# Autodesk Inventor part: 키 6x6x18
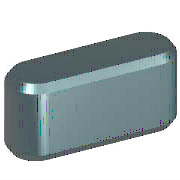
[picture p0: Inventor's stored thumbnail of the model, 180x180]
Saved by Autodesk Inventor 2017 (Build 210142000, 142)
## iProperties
IsCustomPart: 0
Created: 2012-02
Part Number: 키 6x6x18
Material: 강철, 연강
Document SubType Name: Modeling
Standard: JIS B 1301
Designer: mdu
Standards Organization: JIS
Language: ko-KR
Size Designation: 6x6x18
Categories: <MemberInstance><Categories><Category DisplayName="샤프트 부품" InternalName="7f7aeb1f-a693-4053-b835-cee3144e0d98" Mnemonic="SHFT"><Category DisplayName="키" Interna
Density: 1 g/cm^3
Appearance: 보라색
Author: mdu
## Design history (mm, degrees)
workplane "Work Plane1"
workplane "Work Plane2"
sketch "스케치1"
  geometry: L1 (3, 3)-(15, 3); L2 (15, -3)-(3, -3); L3 (0, 9.4)-(0, -7.4) reference; L4 (-5, 0)-(30, 0) reference; L5 (18, 0)-(18, 7); A1 r 3 centre (3, 0) between (3, 3) and (3, -3); A2 r 3 centre (15, 0) between (15, -3) and (15, 3)
  constraints: 6 end point, 5 point on circle, 4 tangent, 3 point on line, 2 centre point, 1 horizontal, 1 parallel, 1 perpendicular
  dimensions: "d0" = 3 radius of A1 (= 0.5 x PB); "d13" = 3 radius of A2 (= 0.5 x PB); "d14" = 18 distance between parallel lines of L5 L3 (= NLG)
extrude "본체1" new body sketch "스케치1" taper "d3" = 0 deg; stored distance "d4" = 10
workplane "Work Plane3"
body "Solid1"
chamfer "모따기1" distance "d8" = 0.4 (= PHH); stored, may be unused: second distance "d9" = 0.4 (= PHH), angle "d15" = 45 deg
other parameters: "d1" = -3.5 (= -PNT), "d2" = 2.5 (= PH - PNT), "NLG" = 18 [user parameter; used in 3 equation terms], "PB" = 6 [user parameter; used in 2 equation terms], "PNT" = 3.5 [user parameter; used in 2 equation terms], "PH" = 6 [user parameter; used in 1 equation term], "PHH" = 0.4 [user parameter; used in 2 equation terms], "d10" = 0, "d16" = 0, "d17" = 0, "d18" = 0, "WDMIN" = 17 [user parameter], "PLB2" = 18 (= NLG) [user parameter], "WDMAX" = 22 [user parameter], "PLB1" = 18 (= NLG) [user parameter], "RR" = 0.16 [user parameter], "PUEB" = 2.8 [user parameter]
